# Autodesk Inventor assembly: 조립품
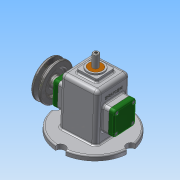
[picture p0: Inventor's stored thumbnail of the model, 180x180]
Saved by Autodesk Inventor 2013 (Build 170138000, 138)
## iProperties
Created: 2018-07
Part Number: 조립품
Document SubType Name: Assembly
Designer: Administrator
Author: Administrator
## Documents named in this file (16)
- C:\Users\Administrator\Desktop\480708V1018\조립품.iam
- C:\Users\Administrator\Desktop\480708V1018\본체.ipt
- C:\Users\Administrator\Desktop\480708V1018\편심축.ipt
- C:\Users\Administrator\Desktop\480708V1018\베어링 12x32x10.ipt
- C:\Users\Administrator\Desktop\480708V1018\앞커버.ipt
- C:\Users\Administrator\Desktop\480708V1018\뒤커버.ipt
- C:\Users\Administrator\Desktop\480708V1018\링크.ipt
- C:\Users\Administrator\Desktop\480708V1018\핀 5x18.ipt
- C:\Users\Administrator\Desktop\480708V1018\슬라이드.ipt
- C:\Users\Administrator\Desktop\480708V1018\부시.ipt
- C:\Users\Administrator\Desktop\480708V1018\오일 실 12 25 7.ipt
- C:\Users\Administrator\Desktop\480708V1018\고정핀 1.2x8.ipt
- C:\Users\Administrator\Desktop\480708V1018\키 4x4x10.ipt
- C:\Users\Administrator\Desktop\480708V1018\멈춤나사 M3x8.ipt
- C:\Users\Administrator\Desktop\480708V1018\V벨트풀리.ipt
- C:\Users\Administrator\Desktop\480708V1018\볼트 M4.ipt
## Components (3 placed, 3 different names)
1. 핀 5x18:1
2. 고정핀 1.2x8:1
3. V벨트풀리:1 — 플러쉬:2
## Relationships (1: Flush 1)
- 플러쉬:2 [Flush]: V벨트풀리:1
